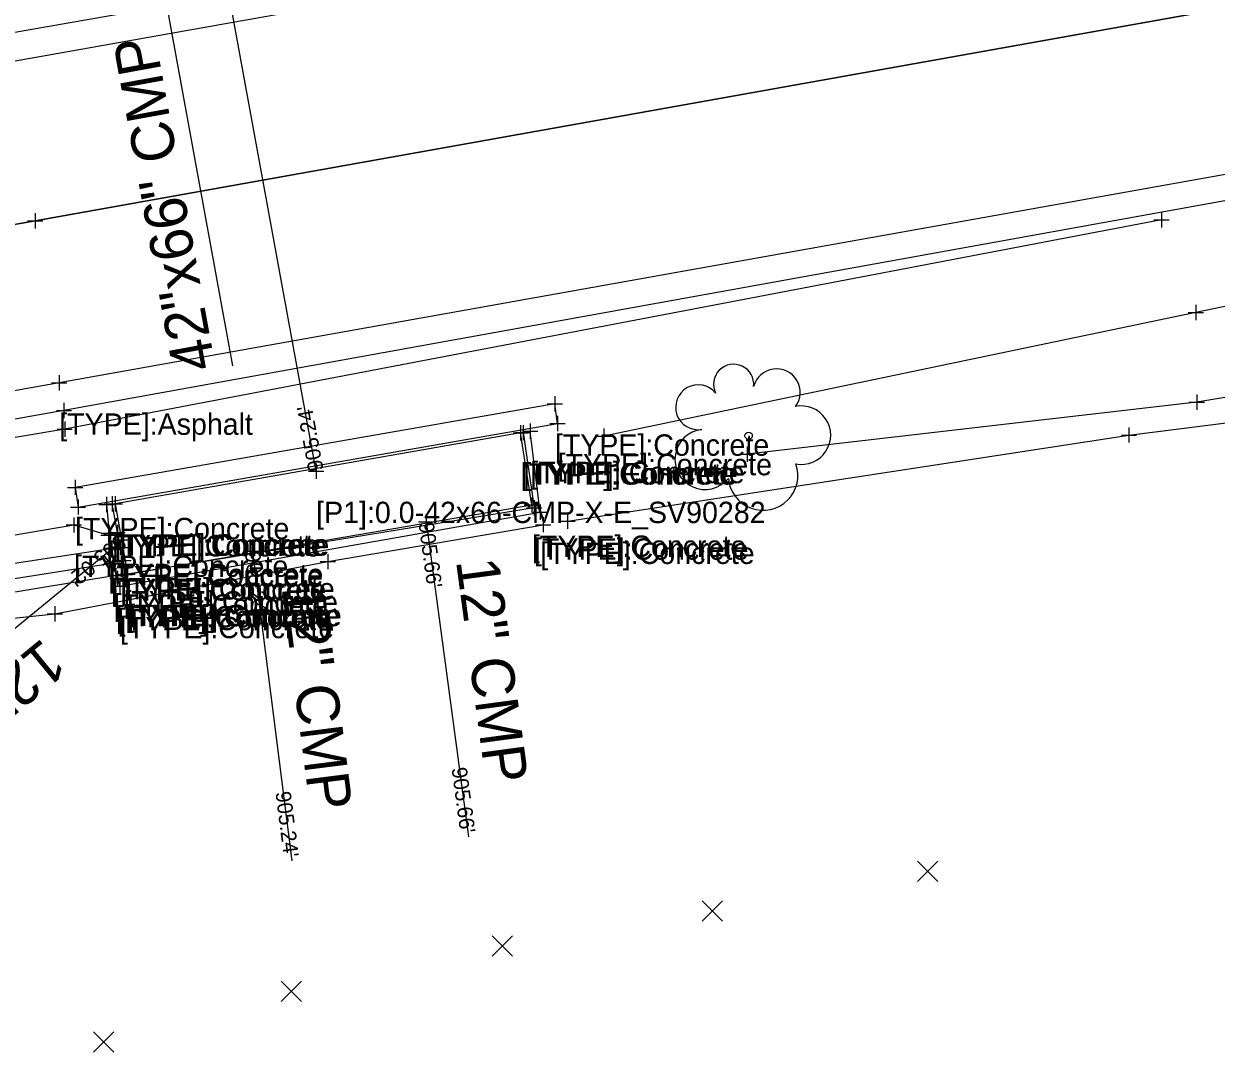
# Model space of a CAD drawing. Extents: x 1386013 to 1389776, y 604170 to 607009.
# Drawn here: x 1388526.5 to 1388604.6, y 604949.8 to 605018.1 of the extents above; entities that cross this region are included whole.
import ezdxf

# ---------------------------------------------------------------- set-up
doc = ezdxf.new("R2010")
doc.units = 0
for name, color, linetype in [('_CIVIL_CONSTRUCTION', 7, 'Continuous'), ('DR_X_Elev_Flow', 7, 'Continuous'), ('DR_X_Headwall', 7, 'Continuous'), ('DR_X_Storm_Sewer', 7, 'Continuous'), ('DR_X_Text', 7, 'Continuous'), ('DV_X_Text', 7, 'Continuous'), ('PM_X_CL_Double_Solid', 7, 'Continuous'), ('PV_X_COP', 7, 'Continuous'), ('PV_X_EOP', 7, 'Continuous'), ('PV_X_Shoulder', 7, 'Continuous'), ('RD_X_Concrete_Pad', 7, 'Continuous'), ('RD_X_Fence', 7, 'Continuous'), ('RD_X_GR_Lt', 7, 'Continuous'), ('RD_X_Wall', 7, 'Continuous'), ('SC_Scratch1', 7, 'Continuous'), ('SV_X_Break_Lines', 7, 'Continuous'), ('SV_X_Random_Point', 7, 'Continuous'), ('SV_X_Text', 7, 'Continuous'), ('SV_X_Toe_of_Slope', 7, 'Continuous'), ('SV_X_Top_of_Bank', 7, 'Continuous')]:
    doc.layers.add(name, color=color, linetype=linetype)

msp = doc.modelspace()

# ---------------------------------------------------------------- linework, layer by layer
at = {"layer": '_CIVIL_CONSTRUCTION'}
msp.add_circle((1388573.942, 604991.131), 0.24, dxfattribs=at)
for centre, radius, start, end in [((1388572.958, 604994.499), 1.317, 354.0047, 205.97412), ((1388575.768, 604993.96), 1.553, 323.82996, 165.0376), ((1388570.633, 604992.995), 1.471, 39.06254, 279.54124), ((1388577.402, 604991.167), 1.915, 259.14531, 101.45961), ((1388571.089, 604989.583), 1.974, 96.17219, 320.57371), ((1388574.888, 604988.526), 2.284, 184.94757, 19.45715)]:
    msp.add_arc(centre, radius, start, end, dxfattribs=at)
at = {"layer": 'DR_X_Elev_Flow'}
for p, q in [((1388552.304, 604985.48), (1388553.304, 604985.48)), ((1388552.804, 604985.98), (1388552.804, 604984.98)), ((1388552.804, 604985.48), (1388552.804, 604985.48)), ((1388532.96, 604984.813), (1388532.96, 604983.813)), ((1388532.46, 604984.313), (1388533.46, 604984.313)), ((1388532.96, 604984.313), (1388532.96, 604984.313)), ((1388541.427, 604984.061), (1388541.427, 604983.061)), ((1388540.927, 604983.561), (1388541.927, 604983.561)), ((1388541.427, 604983.561), (1388541.427, 604983.561))]:
    msp.add_line(p, q, dxfattribs=at)
at = {"layer": 'DR_X_Headwall'}
msp.add_lwpolyline([(1388561.427, 604991.938), (1388561.246, 604993.219), (1388529.807, 604987.747), (1388530.003, 604986.46)], close=True, dxfattribs=at)
at = {"layer": 'DR_X_Storm_Sewer'}
for p, q in [((1388545.603, 604988.805), (1388538.598, 605027.167)), ((1388552.804, 604985.48), (1388555.584, 604964.857)), ((1388532.96, 604984.313), (1388508.623, 604964.379)), ((1388541.427, 604983.561), (1388544.014, 604963.277))]:
    msp.add_line(p, q, dxfattribs=at)
at = {"layer": 'DR_X_Text'}
msp.add_line((1388535.192, 605022.716), (1388540.125, 604995.7), dxfattribs=at)
at = {"layer": 'DV_X_Text'}
for p, q in [((1388601.002, 605005.763), (1388601.002, 605004.763)), ((1388526.687, 605005.201), (1388527.687, 605005.201)), ((1388527.187, 605005.701), (1388527.187, 605004.701)), ((1388527.187, 605005.201), (1388527.187, 605005.201)), ((1388600.502, 605005.263), (1388601.502, 605005.263)), ((1388601.002, 605005.263), (1388601.002, 605005.263)), ((1388603.246, 604999.706), (1388603.246, 604998.706)), ((1388602.746, 604999.206), (1388603.746, 604999.206)), ((1388603.246, 604999.206), (1388603.246, 604999.206)), ((1388528.768, 604995.089), (1388528.768, 604994.089)), ((1388528.268, 604994.589), (1388529.268, 604994.589)), ((1388528.768, 604994.589), (1388528.768, 604994.589)), ((1388529.082, 604993.274), (1388529.082, 604992.274)), ((1388560.746, 604993.219), (1388561.746, 604993.219)), ((1388561.246, 604993.719), (1388561.246, 604992.719)), ((1388561.246, 604993.219), (1388561.246, 604993.219)), ((1388602.81, 604993.329), (1388603.81, 604993.329)), ((1388603.31, 604993.829), (1388603.31, 604992.829)), ((1388603.31, 604993.329), (1388603.31, 604993.329)), ((1388528.582, 604992.774), (1388529.582, 604992.774)), ((1388529.082, 604992.774), (1388529.082, 604992.774)), ((1388561.427, 604992.438), (1388561.427, 604991.438)), ((1388529.128, 604992.058), (1388529.128, 604991.058)), ((1388559.005, 604991.828), (1388559.005, 604990.828)), ((1388559.174, 604991.831), (1388559.174, 604990.831)), ((1388559.634, 604991.922), (1388559.634, 604990.922)), ((1388560.927, 604991.938), (1388561.927, 604991.938)), ((1388561.427, 604991.938), (1388561.427, 604991.938)), ((1388598.862, 604991.677), (1388598.862, 604990.677)), ((1388528.628, 604991.558), (1388529.628, 604991.558)), ((1388529.128, 604991.558), (1388529.128, 604991.558)), ((1388558.505, 604991.328), (1388559.505, 604991.328)), ((1388558.674, 604991.331), (1388559.674, 604991.331)), ((1388559.005, 604991.328), (1388559.005, 604991.328)), ((1388559.134, 604991.422), (1388560.134, 604991.422)), ((1388559.174, 604991.331), (1388559.174, 604991.331)), ((1388559.634, 604991.422), (1388559.634, 604991.422)), ((1388563.963, 604991.101), (1388564.963, 604991.101)), ((1388564.463, 604991.601), (1388564.463, 604990.601)), ((1388564.463, 604991.101), (1388564.463, 604991.101)), ((1388598.362, 604991.177), (1388599.362, 604991.177)), ((1388598.862, 604991.177), (1388598.862, 604991.177)), ((1388573.837, 604990.419), (1388573.837, 604989.419)), ((1388545.603, 604989.305), (1388545.603, 604988.305)), ((1388573.337, 604989.919), (1388574.337, 604989.919)), ((1388573.837, 604989.919), (1388573.837, 604989.919)), ((1388545.103, 604988.805), (1388546.103, 604988.805)), ((1388545.603, 604988.805), (1388545.603, 604988.805)), ((1388529.307, 604987.747), (1388530.307, 604987.747)), ((1388529.807, 604988.247), (1388529.807, 604987.247)), ((1388529.807, 604987.747), (1388529.807, 604987.747)), ((1388530.003, 604986.96), (1388530.003, 604985.96)), ((1388531.864, 604987.12), (1388531.864, 604986.12)), ((1388532.248, 604987.16), (1388532.248, 604986.16)), ((1388532.426, 604987.175), (1388532.426, 604986.175)), ((1388559.742, 604987.092), (1388559.742, 604986.092)), ((1388529.503, 604986.46), (1388530.503, 604986.46)), ((1388530.003, 604986.46), (1388530.003, 604986.46)), ((1388531.364, 604986.62), (1388532.364, 604986.62)), ((1388531.748, 604986.66), (1388532.748, 604986.66)), ((1388531.864, 604986.62), (1388531.864, 604986.62)), ((1388531.926, 604986.675), (1388532.926, 604986.675)), ((1388532.248, 604986.66), (1388532.248, 604986.66)), ((1388532.426, 604986.675), (1388532.426, 604986.675)), ((1388559.242, 604986.592), (1388560.242, 604986.592)), ((1388559.385, 604986.404), (1388560.385, 604986.404)), ((1388559.742, 604986.592), (1388559.742, 604986.592)), ((1388559.885, 604986.904), (1388559.885, 604985.904)), ((1388559.885, 604986.404), (1388559.885, 604986.404)), ((1388560.287, 604986.628), (1388560.287, 604985.628)), ((1388529.734, 604985.782), (1388529.734, 604984.782)), ((1388559.787, 604986.128), (1388560.787, 604986.128)), ((1388560.287, 604986.128), (1388560.287, 604986.128)), ((1388560.479, 604985.802), (1388560.479, 604984.802)), ((1388561.574, 604985.531), (1388562.574, 604985.531)), ((1388562.074, 604986.031), (1388562.074, 604985.031)), ((1388562.074, 604985.531), (1388562.074, 604985.531)), ((1388529.234, 604985.282), (1388530.234, 604985.282)), ((1388529.734, 604985.282), (1388529.734, 604985.282)), ((1388531.536, 604984.739), (1388532.536, 604984.739)), ((1388531.995, 604985.106), (1388531.995, 604984.106)), ((1388532.036, 604985.239), (1388532.036, 604984.239)), ((1388532.036, 604984.739), (1388532.036, 604984.739)), ((1388532.082, 604984.792), (1388533.082, 604984.792)), ((1388532.582, 604985.292), (1388532.582, 604984.292)), ((1388532.582, 604984.792), (1388532.582, 604984.792)), ((1388559.979, 604985.302), (1388560.979, 604985.302)), ((1388560.479, 604985.302), (1388560.479, 604985.302)), ((1388531.495, 604984.606), (1388532.495, 604984.606)), ((1388531.995, 604984.606), (1388531.995, 604984.606)), ((1388532.14, 604984.24), (1388532.14, 604983.24)), ((1388532.167, 604984.257), (1388532.167, 604983.257)), ((1388532.227, 604984.227), (1388532.227, 604983.227)), ((1388532.778, 604984.302), (1388532.778, 604983.302)), ((1388531.64, 604983.74), (1388532.64, 604983.74)), ((1388531.667, 604983.757), (1388532.667, 604983.757)), ((1388531.727, 604983.727), (1388532.727, 604983.727)), ((1388532.14, 604983.74), (1388532.14, 604983.74)), ((1388532.167, 604983.757), (1388532.167, 604983.757)), ((1388532.227, 604983.727), (1388532.227, 604983.727)), ((1388532.278, 604983.802), (1388533.278, 604983.802)), ((1388532.34, 604983.243), (1388532.34, 604982.243)), ((1388532.343, 604983.272), (1388532.343, 604982.272)), ((1388532.778, 604983.802), (1388532.778, 604983.802)), ((1388532.986, 604983.447), (1388532.986, 604982.447)), ((1388546.37, 604983.381), (1388546.37, 604982.381)), ((1388531.84, 604982.743), (1388532.84, 604982.743)), ((1388531.843, 604982.772), (1388532.843, 604982.772)), ((1388532.34, 604982.743), (1388532.34, 604982.743)), ((1388532.343, 604982.772), (1388532.343, 604982.772)), ((1388532.483, 604982.469), (1388532.483, 604981.469)), ((1388532.486, 604982.947), (1388533.486, 604982.947)), ((1388532.596, 604982.288), (1388532.596, 604981.288)), ((1388532.986, 604982.947), (1388532.986, 604982.947)), ((1388533.098, 604982.535), (1388533.098, 604981.535)), ((1388533.239, 604982.561), (1388533.239, 604981.561)), ((1388545.87, 604982.881), (1388546.87, 604982.881)), ((1388546.37, 604982.881), (1388546.37, 604982.881)), ((1388531.983, 604981.969), (1388532.983, 604981.969)), ((1388532.096, 604981.788), (1388533.096, 604981.788)), ((1388532.483, 604981.969), (1388532.483, 604981.969)), ((1388532.596, 604981.788), (1388532.596, 604981.788)), ((1388532.598, 604982.035), (1388533.598, 604982.035)), ((1388532.739, 604982.061), (1388533.739, 604982.061)), ((1388532.742, 604981.765), (1388532.742, 604980.765)), ((1388533.098, 604982.035), (1388533.098, 604982.035)), ((1388533.239, 604982.061), (1388533.239, 604982.061)), ((1388532.242, 604981.265), (1388533.242, 604981.265)), ((1388532.742, 604981.265), (1388532.742, 604981.265)), ((1388528.476, 604979.959), (1388528.476, 604978.959)), ((1388527.976, 604979.459), (1388528.976, 604979.459)), ((1388528.476, 604979.459), (1388528.476, 604979.459))]:
    msp.add_line(p, q, dxfattribs=at)
at = {"layer": 'PM_X_CL_Double_Solid'}
msp.add_lwpolyline([(1387998.852, 604914.969), (1388072.268, 604927.437), (1388150.341, 604940.542), (1388219.828, 604952.561), (1388327.209, 604971.051), (1388378.925, 604979.712), (1388451.752, 604991.987), (1388527.187, 605005.201), (1388605.277, 605019.172), (1388650.042, 605026.963), (1388727.22, 605040.353), (1388785.545, 605050.583), (1388850.552, 605062.12), (1388924.492, 605075.022), (1388990.903, 605086.799), (1389068.675, 605100.876), (1389141.896, 605114.3), (1389207.534, 605126.394), (1389280.368, 605139.486)], dxfattribs=at)
at = {"layer": 'PV_X_COP'}
msp.add_lwpolyline([(1389280.368, 605139.486), (1389207.534, 605126.394), (1389141.896, 605114.3), (1389068.675, 605100.876), (1388990.903, 605086.799), (1388924.492, 605075.022), (1388850.552, 605062.12), (1388785.545, 605050.583), (1388727.22, 605040.353), (1388650.042, 605026.963), (1388605.277, 605019.172), (1388527.187, 605005.201), (1388451.752, 604991.987), (1388378.925, 604979.712), (1388327.209, 604971.051), (1388219.828, 604952.561), (1388150.341, 604940.542), (1388072.268, 604927.437), (1387998.852, 604914.969)], dxfattribs=at)
at = {"layer": 'PV_X_EOP'}
for points in [[(1389278.608, 605149.893), (1389205.624, 605136.539), (1389139.992, 605124.612), (1389067.035, 605111.385), (1388989.39, 605097.254), (1388922.829, 605085.432), (1388849.856, 605072.554), (1388784.246, 605061.078), (1388726.082, 605050.998), (1388647.729, 605037.352), (1388603.872, 605029.522), (1388525.264, 605015.568), (1388450.623, 605002.623), (1388377.287, 604990.075), (1388325.535, 604981.408), (1388218.944, 604963.013), (1388149.684, 604951.266), (1388070.904, 604937.92), (1387997.667, 604925.455)], [(1389281.266, 605129.056), (1389208.504, 605115.448), (1389143.415, 605103.484), (1389070.144, 605089.918), (1388993.292, 605076.097), (1388925.014, 605063.953), (1388851.698, 605051.174), (1388786.307, 605039.62), (1388729.797, 605029.749), (1388651.589, 605016.287), (1388606.273, 605008.433), (1388528.768, 604994.589), (1388453.601, 604981.361), (1388380.253, 604968.934), (1388328.493, 604960.284), (1388221.371, 604941.869), (1388151.139, 604929.781), (1388073.477, 604916.736), (1388000.199, 604904.184)]]:
    msp.add_lwpolyline(points, dxfattribs=at)
at = {"layer": 'PV_X_Shoulder'}
for points in [[(1389278.317, 605151.375), (1389205.256, 605138.274), (1389139.516, 605126.2), (1389066.772, 605113.201), (1388989.159, 605098.99), (1388922.81, 605087.133), (1388849.396, 605074.384), (1388802.288, 605066.592), (1388793.594, 605066.344), (1388786.161, 605070.011), (1388734.228, 605060.313), (1388725.783, 605053.304), (1388647.708, 605038.745), (1388603.544, 605031.123), (1388524.83, 605017.377), (1388449.884, 605004.12), (1388377.375, 604991.893), (1388326.153, 604983.278), (1388218.459, 604964.952), (1388149.618, 604953.156), (1388070.878, 604939.746), (1387997.08, 604927.243)], [(1389070.296, 605088.444), (1388993.76, 605074.508), (1388925.138, 605062.29), (1388851.877, 605049.708), (1388786.621, 605037.962), (1388729.921, 605028.263), (1388651.514, 605014.412), (1388606.715, 605006.792), (1388529.082, 604992.774), (1388453.763, 604979.448), (1388380.57, 604967.56), (1388328.474, 604958.579), (1388293.068, 604951.047), (1388291.513, 604952.099), (1388221.653, 604940.356), (1388151.367, 604928.17), (1388118.449, 604921.915), (1388113.87, 604918.914), (1388113.301, 604917.195), (1388092.337, 604913.819), (1388086.608, 604916.749), (1388073.661, 604915.378), (1388000.633, 604902.689)]]:
    msp.add_lwpolyline(points, dxfattribs=at)
at = {"layer": 'RD_X_Concrete_Pad'}
for points in [[(1388532.426, 604986.675), (1388533.239, 604982.061), (1388559.742, 604986.592), (1388559.005, 604991.328)], [(1388511.569, 604978.518), (1388512.105, 604979.582), (1388511.41, 604980.542), (1388511.231, 604982.157), (1388529.734, 604985.282), (1388531.995, 604984.606), (1388532.167, 604983.757), (1388532.483, 604981.969)]]:
    msp.add_lwpolyline(points, close=True, dxfattribs=at)
at = {"layer": 'RD_X_Fence'}
msp.add_lwpolyline([(1388723.317, 605013.645), (1388651.119, 605001.335), (1388603.31, 604993.329), (1388573.837, 604989.919)], dxfattribs=at)
at = {"layer": 'RD_X_GR_Lt'}
msp.add_lwpolyline([(1388601.002, 605005.263), (1388529.128, 604991.558), (1388479.569, 604983.232)], dxfattribs=at)
at = {"layer": 'RD_X_Wall'}
msp.add_lwpolyline([(1388532.248, 604986.66), (1388531.864, 604986.62), (1388532.036, 604984.739), (1388532.227, 604983.727), (1388532.34, 604982.743), (1388532.596, 604981.788), (1388532.742, 604981.265), (1388560.287, 604986.128), (1388559.634, 604991.422), (1388559.174, 604991.331), (1388559.885, 604986.404), (1388533.098, 604982.035), (1388532.986, 604982.947), (1388532.778, 604983.802), (1388532.582, 604984.792)], close=True, dxfattribs=at)
at = {"layer": 'SV_X_Break_Lines'}
msp.add_lwpolyline([(1388490.907, 604974.548), (1388512.621, 604977.803), (1388528.476, 604979.459), (1388546.37, 604982.881), (1388560.479, 604985.302)], dxfattribs=at)
msp.add_lwpolyline([(1388512.1, 604979.589), (1388511.413, 604980.574), (1388532.14, 604983.74), (1388532.343, 604982.772)], close=True, dxfattribs=at)
at = {"layer": 'SV_X_Random_Point'}
for p, q in [((1388585.012, 604961.928), (1388586.346, 604963.263)), ((1388585.012, 604963.263), (1388586.346, 604961.928)), ((1388570.906, 604959.328), (1388572.24, 604960.663)), ((1388570.906, 604960.663), (1388572.24, 604959.328)), ((1388557.137, 604957.036), (1388558.471, 604958.371)), ((1388557.137, 604958.371), (1388558.471, 604957.036)), ((1388543.305, 604954.069), (1388544.639, 604955.404)), ((1388543.305, 604955.404), (1388544.639, 604954.069)), ((1388531.009, 604950.745), (1388532.343, 604952.08)), ((1388531.009, 604952.08), (1388532.343, 604950.745))]:
    msp.add_line(p, q, dxfattribs=at)
at = {"layer": 'SV_X_Toe_of_Slope'}
msp.add_lwpolyline([(1388981.597, 605067.689), (1388926.155, 605057.232), (1388852.377, 605043.808), (1388787.457, 605031.997), (1388730.994, 605022.223), (1388651.291, 605009.184), (1388603.246, 604999.206), (1388564.463, 604991.101)], dxfattribs=at)
at = {"layer": 'SV_X_Top_of_Bank'}
msp.add_lwpolyline([(1388562.074, 604985.531), (1388598.862, 604991.177), (1388647.291, 604997.303), (1388724.163, 605010.337), (1388772.209, 605021.872), (1388814.771, 605030.031), (1388888.919, 605043.484), (1388966.26, 605059.038), (1388983.112, 605062.529)], dxfattribs=at)

# ---------------------------------------------------------------- texts
at = {"layer": 'DR_X_Text'}
for s, height, rotation, p in [('42"x66" CMP', 2.79999, 100.34775, (1388539.021, 604995.615)), ('12" CMP', 2.8, 277.67631, (1388554.763, 604982.935)), ('12" CMP', 2.8, 277.2688, (1388543.345, 604981.181)), ('12" CMP', 2.8, 219.3196, (1388527.702, 604977.936))]:
    msp.add_text(s, height=height, rotation=rotation, dxfattribs=at).set_placement(p)
at = {"layer": 'SC_Scratch1'}
for s, rotation, p in [("905.24'", 100.34775, (1388546.094, 604988.895)), ("905.66'", 277.67631, (1388552.308, 604985.413)), ("905.02'", 219.3196, (1388532.643, 604984.7)), ("905.24'", 277.2688, (1388540.931, 604983.498)), ("905.66'", 277.67631, (1388554.474, 604969.347)), ("905.24'", 277.2688, (1388542.937, 604967.774))]:
    msp.add_text(s, height=1, rotation=rotation, dxfattribs=at).set_placement(p)
at = {"layer": 'SV_X_Text'}
for s, p in [('[TYPE]:Asphalt', (1388528.768, 604991.189)), ('[TYPE]:Concrete', (1388561.246, 604989.819)), ('[TYPE]:Concrete', (1388559.005, 604987.928)), ('[TYPE]:Concrete', (1388559.174, 604987.931)), ('[TYPE]:Concrete', (1388559.634, 604988.022)), ('[TYPE]:Concrete', (1388561.427, 604988.538)), ('[P1]:0.0-42x66-CMP-X-E_SV90282', (1388545.603, 604985.405)), ('[TYPE]:Concrete', (1388529.807, 604984.347)), ('[TYPE]:Concrete', (1388531.864, 604983.22)), ('[TYPE]:Concrete', (1388532.248, 604983.26)), ('[TYPE]:Concrete', (1388532.426, 604983.275)), ('[TYPE]:Concrete', (1388559.742, 604983.192)), ('[TYPE]:Concrete', (1388559.885, 604983.004)), ('[TYPE]:Concrete', (1388560.287, 604982.728)), ('[TYPE]:Concrete', (1388529.734, 604981.882)), ('[TYPE]:Concrete', (1388531.995, 604981.206)), ('[TYPE]:Concrete', (1388532.036, 604981.339)), ('[TYPE]:Concrete', (1388532.167, 604980.357)), ('[TYPE]:Concrete', (1388532.227, 604980.327)), ('[TYPE]:Concrete', (1388532.778, 604980.402)), ('[TYPE]:Concrete', (1388532.34, 604979.343)), ('[TYPE]:Concrete', (1388532.986, 604979.547)), ('[TYPE]:Concrete', (1388532.483, 604978.569)), ('[TYPE]:Concrete', (1388533.098, 604978.635)), ('[TYPE]:Concrete', (1388533.239, 604978.661)), ('[TYPE]:Concrete', (1388532.596, 604978.388)), ('[TYPE]:Concrete', (1388532.742, 604977.865))]:
    msp.add_text(s, height=1.4, dxfattribs=at).set_placement(p)

doc.saveas('drawing.dxf')
